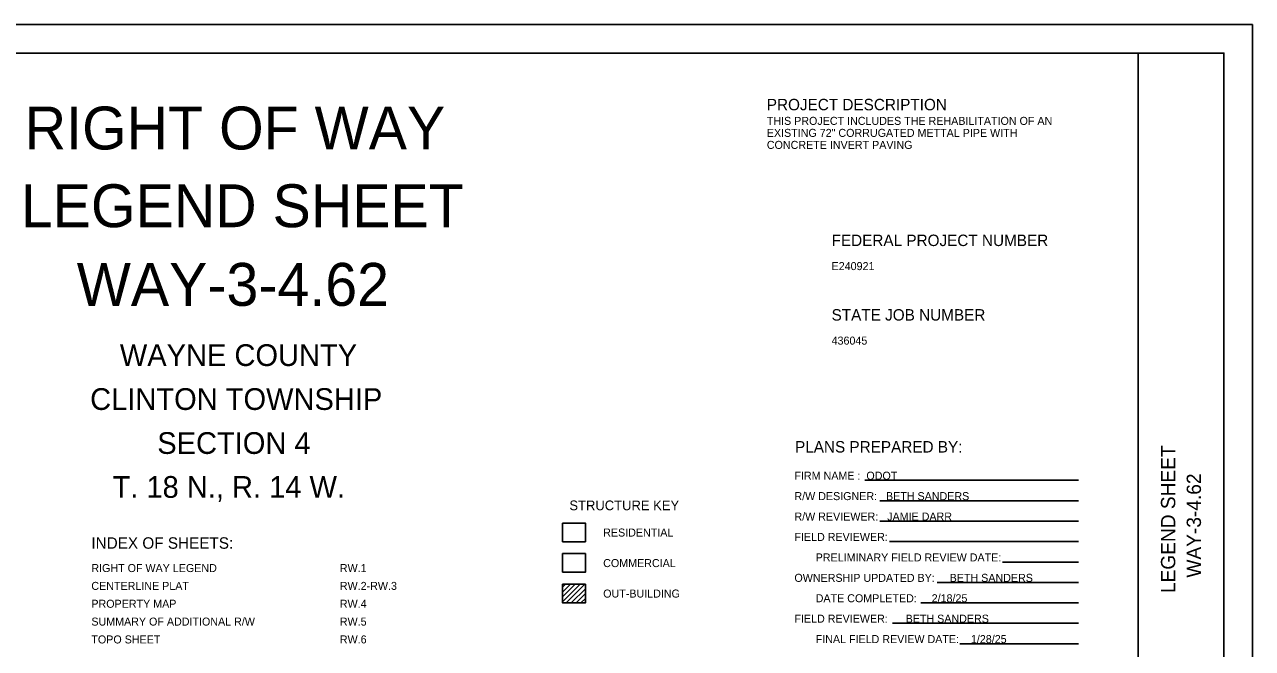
# Model space of a CAD drawing. Extents: x 0 to 34, y 0 to 22.
# Drawn here: x 12.52 to 34, y 11.09 to 22 of the extents above; entities that cross this region are included whole.
import ezdxf

# ---------------------------------------------------------------- set-up
doc = ezdxf.new("R2010")
doc.units = 0
for name, color, linetype in [('SC_Shading1', 7, 'Continuous'), ('SH_Border', 7, 'Continuous'), ('SH_Cut_Line', 7, 'Continuous'), ('SH_Data', 7, 'Continuous'), ('SH_Text', 7, 'Continuous')]:
    doc.layers.add(name, color=color, linetype=linetype)

msp = doc.modelspace()

# ---------------------------------------------------------------- linework, layer by layer
at = {"layer": 'SC_Shading1'}
msp.add_lwpolyline([(21.935, 12.423), (22.332, 12.423), (22.332, 12.749), (21.935, 12.749)], close=True, dxfattribs=at)
at = {"layer": 'SH_Border'}
msp.add_line((32, 0.5), (32, 21.5), dxfattribs=at)
msp.add_lwpolyline([(1.5, 21.5), (33.5, 21.5), (33.5, 0.5), (1.5, 0.5)], close=True, dxfattribs=at)
at = {"layer": 'SH_Cut_Line'}
msp.add_lwpolyline([(0, 0), (34, 0), (34, 22), (0, 22)], close=True, dxfattribs=at)
at = {"layer": 'SH_Text'}
for p, q in [((27.221, 14.032), (30.958, 14.032)), ((27.485, 13.675), (30.958, 13.675)), ((27.485, 13.318), (30.958, 13.318)), ((27.649, 12.961), (30.958, 12.961)), ((29.63, 12.603), (30.958, 12.603)), ((28.485, 12.247), (30.958, 12.247)), ((21.935, 12.212), (21.936, 12.214)), ((21.935, 12.162), (21.987, 12.214)), ((21.935, 12.077), (22.071, 12.214)), ((21.935, 11.993), (22.156, 12.214)), ((21.935, 11.908), (22.241, 12.214)), ((21.999, 11.888), (22.325, 12.214)), ((22.084, 11.888), (22.332, 12.136)), ((22.169, 11.888), (22.332, 12.051)), ((21.935, 11.892), (21.94, 11.888)), ((22.254, 11.888), (22.332, 11.966)), ((28.199, 11.889), (30.958, 11.889)), ((27.702, 11.532), (30.958, 11.532)), ((28.883, 11.175), (30.958, 11.175))]:
    msp.add_line(p, q, dxfattribs=at)
for points in [[(21.935, 13.284), (22.332, 13.284), (22.332, 12.958), (21.935, 12.958)], [(21.935, 12.214), (22.332, 12.214), (22.332, 11.888), (21.935, 11.888)]]:
    msp.add_lwpolyline(points, close=True, dxfattribs=at)

# ---------------------------------------------------------------- texts
at = {"layer": 'SH_Data'}
for s, height, p in [('RIGHT OF WAY', 0.75, (12.527, 19.816)), ('LEGEND SHEET', 0.75, (12.458, 18.457)), ('  WAY-3-4.62 ', 0.75, (12.879, 17.082)), ('      WAYNE COUNTY     ', 0.38, (13.343, 16.03)), ('    CLINTON TOWNSHIP   ', 0.38, (13.106, 15.262)), ('       SECTION 4       ', 0.38, (13.856, 14.493)), ('   T. 18 N., R. 14 W.  ', 0.38, (13.639, 13.725)), ('INDEX OF SHEETS:', 0.2, (13.692, 12.835)), ('RIGHT OF WAY LEGEND                ', 0.14, (13.692, 12.427)), ('RW.1  ', 0.14, (18.038, 12.427)), ('CENTERLINE PLAT                    ', 0.14, (13.692, 12.115)), ('RW.2-RW.3 ', 0.14, (18.038, 12.115)), ('PROPERTY MAP                       ', 0.14, (13.692, 11.803)), ('RW.4  ', 0.14, (18.038, 11.803)), ('SUMMARY OF ADDITIONAL R/W          ', 0.14, (13.692, 11.491)), ('RW.5  ', 0.14, (18.038, 11.491)), ('TOPO SHEET                         ', 0.14, (13.692, 11.179)), ('RW.6  ', 0.14, (18.038, 11.179))]:
    msp.add_text(s, height=height, dxfattribs=at).set_placement(p)
for s, p in [('LEGEND SHEET', (32.65, 12.06)), ('WAY-3-4.62', (33.1, 12.33))]:
    msp.add_text(s, height=0.25, rotation=90, dxfattribs=at).set_placement(p)
at = {"layer": 'SH_Text'}
for s, height, p in [('PROJECT DESCRIPTION', 0.2, (25.506, 20.501)), ('THIS PROJECT INCLUDES THE REHABILITATION OF AN', 0.14, (25.506, 20.246)), ('EXISTING 72" CORRUGATED METTAL PIPE WITH ', 0.14, (25.506, 20.036)), ('CONCRETE INVERT PAVING', 0.14, (25.506, 19.826)), ('FEDERAL PROJECT NUMBER', 0.2, (26.639, 18.127)), ('E240921   ', 0.14, (26.639, 17.707)), ('STATE JOB NUMBER', 0.2, (26.639, 16.824)), ('436045    ', 0.14, (26.639, 16.404)), ('PLANS PREPARED BY:', 0.2, (26, 14.517)), ('FIRM NAME :  ODOT', 0.14, (25.989, 14.042)), ('R/W DESIGNER:   BETH SANDERS', 0.14, (25.989, 13.685)), ('STRUCTURE KEY', 0.17, (22.053, 13.508)), ('R/W REVIEWER:   JAMIE DARR', 0.14, (25.989, 13.328)), ('RESIDENTIAL', 0.14, (22.644, 13.048)), ('FIELD REVIEWER:   ', 0.14, (25.989, 12.971)), ('PRELIMINARY FIELD REVIEW DATE:', 0.14, (26.361, 12.613)), ('COMMERCIAL', 0.14, (22.644, 12.514)), ('OWNERSHIP UPDATED BY:     BETH SANDERS', 0.14, (25.989, 12.256)), ('OUT-BUILDING', 0.14, (22.644, 11.981)), ('DATE COMPLETED:     2/18/25', 0.14, (26.361, 11.899)), ('FIELD REVIEWER:      BETH SANDERS', 0.14, (25.989, 11.542)), ('FINAL FIELD REVIEW DATE:    1/28/25', 0.14, (26.361, 11.185))]:
    msp.add_text(s, height=height, dxfattribs=at).set_placement(p)

doc.saveas('drawing.dxf')
